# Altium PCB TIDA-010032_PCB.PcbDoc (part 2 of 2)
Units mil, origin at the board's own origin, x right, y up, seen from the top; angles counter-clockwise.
Board outline 5930.03 x 5930.03 mil, 2 copper layers (Top Layer, Bottom Layer), stack 62 mil thick; 61 components, 49 nets, 261 pads, 71 vias.
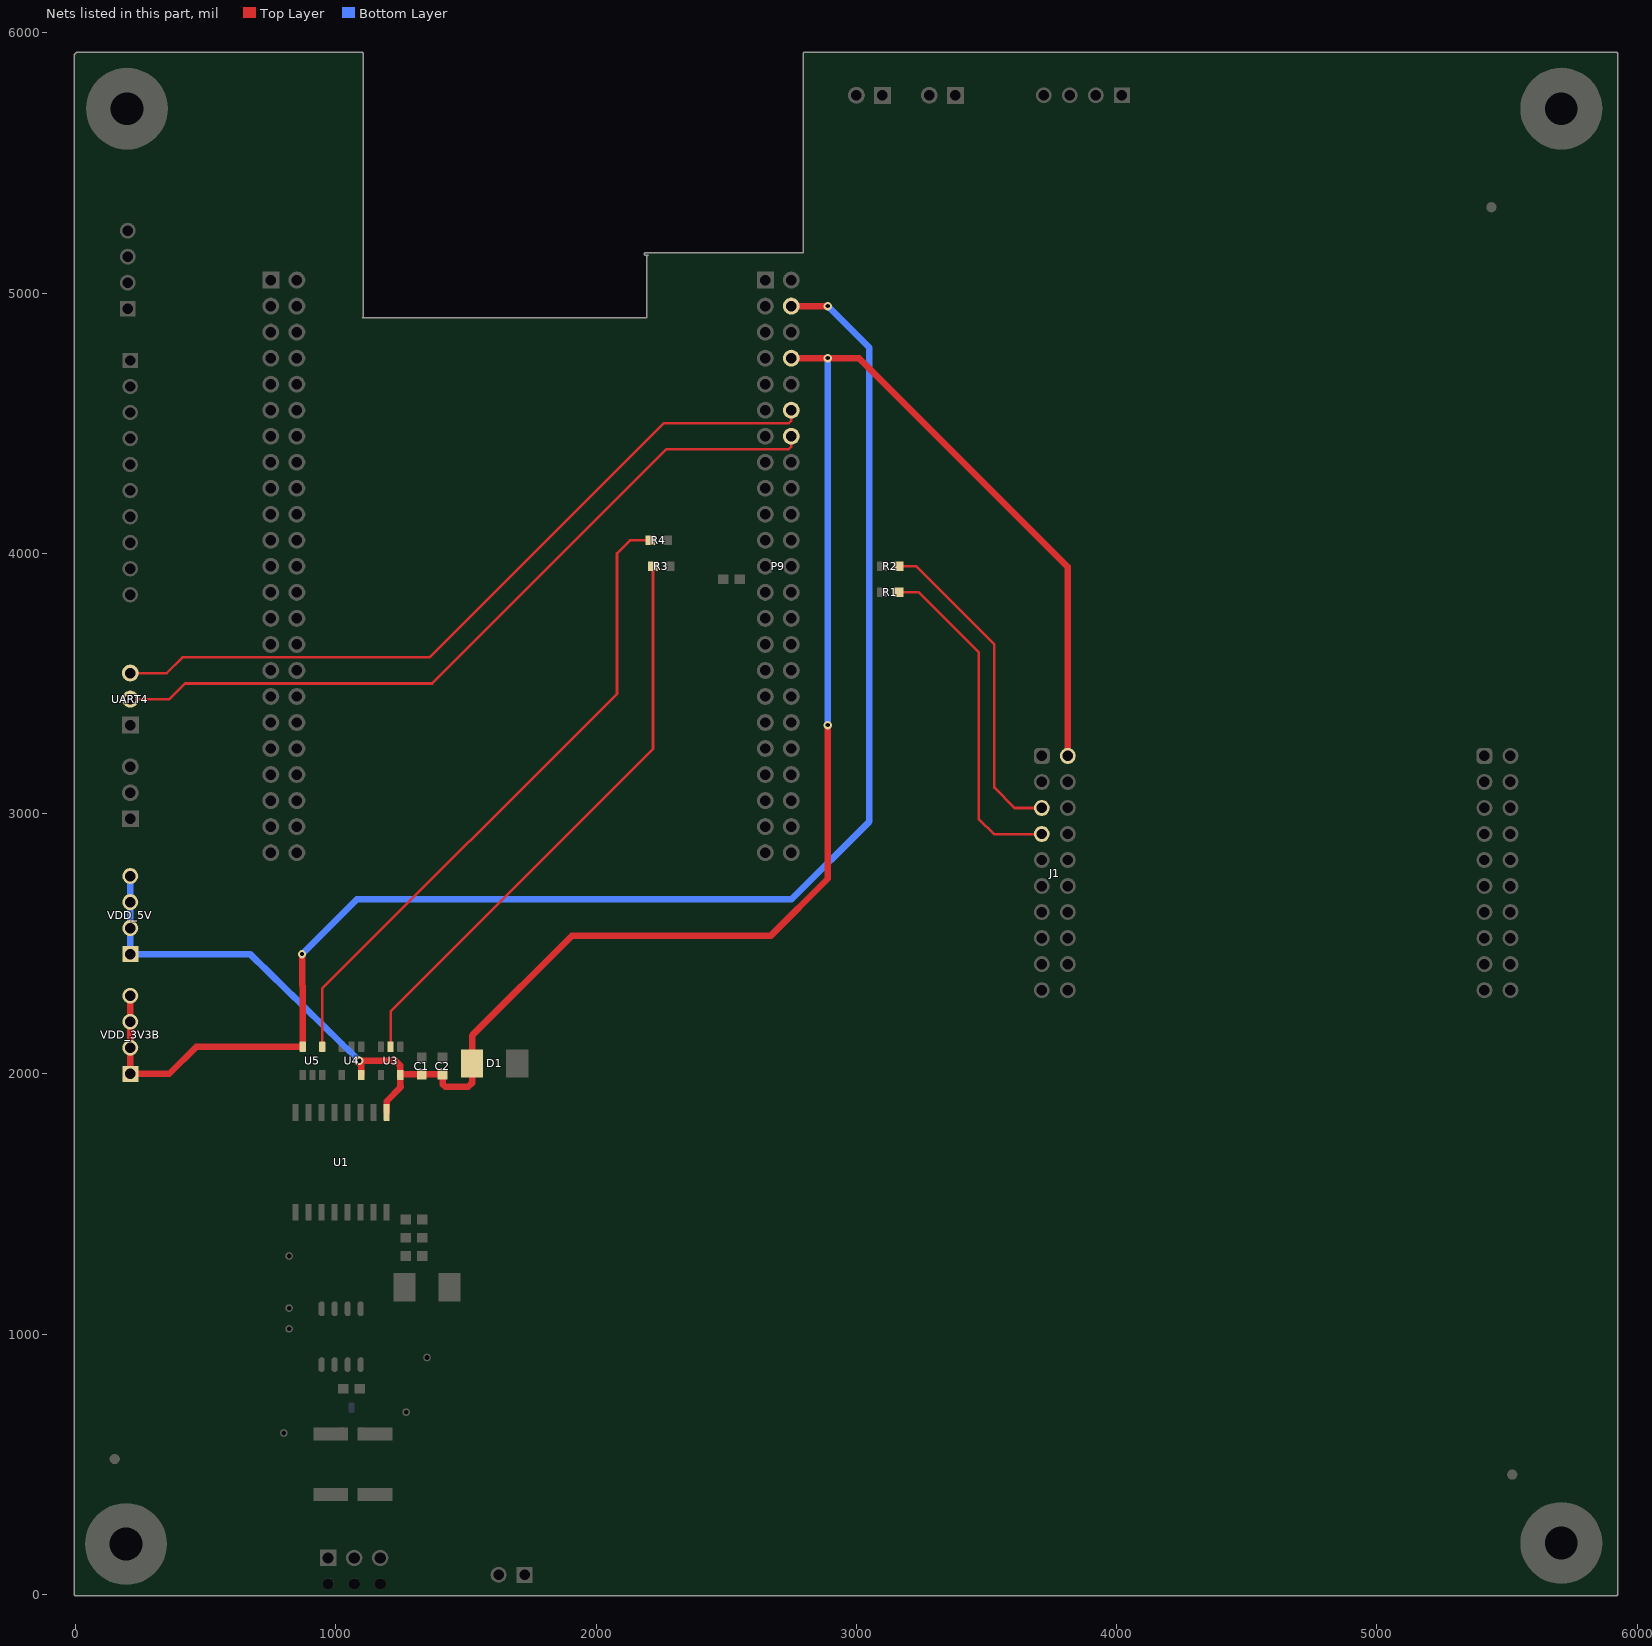
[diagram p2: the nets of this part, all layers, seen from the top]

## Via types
v1: diameter 32, hole 16, Top Layer to Bottom Layer, 71 vias

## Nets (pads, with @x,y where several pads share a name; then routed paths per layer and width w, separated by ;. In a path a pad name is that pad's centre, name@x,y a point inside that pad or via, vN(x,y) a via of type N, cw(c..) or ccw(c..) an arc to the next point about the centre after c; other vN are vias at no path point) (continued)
SYS_5V: C1.1 C2.2 D1.1 J1.2 P9.8 U1.1 U3.5 U4.5 VDD_5V.1 VDD_5V.2 VDD_5V.3 VDD_5V.4 | length 8014.7
  Top Layer w25: U4.5@1097.4,1995.87 1097.4,2032.6 1090,2040 v1(1090,2050) 1229.69,2050 1247.4,2032.28 U3.5@1247.4,1995.87 1247.4,1952.6 1250,1950 1195,1895 U1.1@1195,1851.93 ; U3.5@1250.04,1998.5 C1.1@1330,1998.5 C2.2@1410,1998.5 1410,1960 1420,1950 1508.5,1950 1522.99,1964.49 D1.1@1522.99,2040 1522.99,2147.01 1905.98,2530 2670,2530 2890,2750 v1(2890,3340) ; P9.8@2750,4750 v1(2890,4750) 3010,4750 3812.5,3947.5 3812.5,3812.2 J1.2@3812.5,3221.65
  Bottom Layer w25: VDD_5V.4@210,2760 VDD_5V.3@210,2660 VDD_5V.2@210,2560 VDD_5V.1@210,2460 670,2460 v1(1090,2050) ; v1(2890,3340) v1(2890,4750)
UART1_RXD: J1.7 R1.1 | length 1311.8
  Top Layer w10: R1.1@3161.5,3850 3240,3850 3470,3620 3470,2980 3530,2920 3710.84,2920 J1.7@3712.5,2921.65
UART1_TXD: J1.5 R2.1 | length 1257.7
  Top Layer w10: R2.1@3161.5,3950 3230,3950 3530,3650 3530,3100 3608.35,3021.65 J1.5@3712.5,3021.65
UART2_RXD: R4.1 U5.4 | length 2514.2
  Top Layer w10: U5.4@947.4,2104.13 947.4,2327.4 2080,3460 2080,4000 2130,4050 R4.1@2208.5,4050
UART2_TXD: R3.2 U3.2 | length 2263.6
  Top Layer w10: U3.2@1210,2104.13 1210,2240 2218.5,3248.5 R3.2@2218.5,3950
UART4_RXD: P9.12 UART4.3 | length 2981.8
  Top Layer w10: UART4.3@210,3540 350,3540 410,3600 1360,3600 2260,4500 2740,4500 2750,4510 P9.12@2750,4550
UART4_TXD: P9.14 UART4.2 | length 2981.8
  Top Layer w10: UART4.2@210,3440 360,3440 420,3500 1370,3500 2270,4400 2740,4400 2750,4410 P9.14@2750,4450
VDD_3V3B: P9.4 U5.5 VDD_3V3B.1 VDD_3V3B.2 VDD_3V3B.3 VDD_3V3B.4 | length 5940.2
  Top Layer w25: VDD_3V3B.4@210,2300 VDD_3V3B.3@210,2200 VDD_3V3B.2@210,2100 VDD_3V3B.1@210,2000 360,2000 464.13,2104.13 U5.5@872.6,2104.13 872.6,2337.4 870,2340 v1(870,2460) ; P9.4@2750,4950 v1(2890,4950)
  Bottom Layer w25: v1(870,2460) 1080,2670 2750,2670 3050,2970 3050,4790 v1(2890,4950)
pads on no net: FID1.1 FID2.1 FID3.1 H1.1 H2.1 H3.1 H4.1 J1.1 J1.3 J1.6 J1.8 J1.9 J1.10 J1.11 J1.12 J1.13 J1.14 J1.15 J1.16 J1.17 J1.18 J1.19 J1.20 J2.1 J2.3 J2.4 J2.5 J2.6 J2.7 J2.8 J2.9 J2.10 J2.11 J2.12 J2.13 J2.14 J2.15 J2.16 J2.17 J2.18 J2.19 J2.20 J3.4 J3.5 J3.6 P8.7 P8.8 P8.9 P8.10 P8.11 P8.12 P8.13 P8.14 P8.15 P8.16 P8.17 P8.18 P8.20 P8.25 P8.27 P8.28 P8.29 P8.30 P8.31 P8.32 P8.33 P8.34 P8.35 P8.36 P8.37 P8.38 P8.39 P8.40 P8.41 P8.42 P8.43 P8.44 P8.45 P8.46 P9.3 P9.5 P9.6 P9.7 P9.9 P9.10 P9.13 P9.15 P9.26 P9.31 P9.33 P9.34 P9.35 P9.36 P9.37 P9.38 P9.39 P9.40 P9.41 P9.42 U1.7 U3.1 U4.1 U5.1

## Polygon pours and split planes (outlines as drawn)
DGND on Top Layer "TOP_LAYER_DGND_P004" (solid, remove dead copper, pour order 4): -4.99,1829.69 0,1830 634.98,1830 1290,1830 2600.03,1830 2820,1829.69 3800,1110 3790,1100 3790,0 5910,0 5900,10 5900,5915.02 2800,5920 2800,5140 2199.45,5140 2199.45,4900.55 1105.02,4900.55 1095.8,5922.74 0,5915.02
RS485_GND on Top Layer "TOP_LAYER_RS485_GND_P000" (solid, remove dead copper, pour order 0): 0,1490 520,1490 790,1490 920,1490 1053.07,1490 1203.07,1490 1450,1490 1962.43,1019.97 1962.43,-0.03 12.43,-0.03 2.43,9.97
DGND on Bottom Layer "BOTTOM_LAYER_DGND_P006" (solid, remove dead copper, pour order 6): 0,1830 2820,1830 3790,1120 3790,1110 3790,0 3800,10 5910,10 5910,5900 5900,5910 5890,5920 2800,5910 0,5920
RS485_GND on Bottom Layer "BOTTOM_LAYER_RS485_GND_P002" (solid, remove dead copper, pour order 2): 0,1490 700,1490 1020,1490 1450,1490 1960,1019.97 1960,20 1809.53,20 0,20 0,2109.53

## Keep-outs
Keep-Out Layer:
  text ".Layer_Name" at 577,-858.49 h60

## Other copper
Top Layer:
  text ".Layer_Name" at 577,-858.49 h60
Bottom Layer:
  text ".Layer_Name" at 577,-858.49 h60

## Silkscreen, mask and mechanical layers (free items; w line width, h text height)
Top Overlay:
  region: 3930,160 3630,160 3630,60 3930,60
  text "SCA" at 2950,5660 h50.84
  text "SCL" at 3060,5660 h50.84
  text "SCA" at 3230,5660 h50.84
  text "SCL" at 3340,5660 h50.84
  text "CS0" at 3680,5660 h50.84
  text "D1" at 3790,5660 h50.84
  text "D0" at 3890.76,5659.24 h50.84
  text "SCLK" at 3970,5650 h50.84
  text "2" at 730,5120 h50.84
  text "1" at 840,5120 h50.84
  text "DGND" at 530,5040 h50.84
  text "DGND" at 930,5040 h50.84
  text "2" at 2540,5040 h50.84
  text "1" at 2830,5040 h50.84
  text "DGND" at 2950,5040 h72.83
  text "DGND" at 2310,5032.5 h72.83
  text "VDD_3V3B" at 2240,4930 h72.83
  text "VDD_3V3B" at 2950,4930 h72.83
  text "VDD_5V" at 2310,4830 h72.83
  text "VDD_5V" at 2950,4830 h72.83
  text "SYS_5V" at 2310,4740 h72.83
  text "SYS_5V" at 2950,4730 h72.83
  text "D7" at 300,4720 h50.84 r90
  text "D6" at 300,4620 h50.84 r90
  text "D5" at 299.74,4513.5 h50.84 r90
  text "D4" at 300,4420 h50.84 r90
  text "D3" at 300,4320 h50.84 r90
  text "BeagleBone Black" at 1410,4240 h72.83
  text "D2" at 299.19,4219.32 h50.84 r90
  text "D1" at 300,4120 h50.84 r90
  text "D0" at 300,4020 h50.84 r90
  text "CMD" at 300,3890 h50.84 r90
  text "CLK" at 300,3780 h50.84 r90
  text "RX" at 339.74,3512 h50.84 r90
  text "TX" at 339.74,3412 h50.84 r90
  text "J1" at 3680,3370 h72.83
  text "J2" at 5370,3370 h72.83
  text "1" at 3710,3320 h50.84
  text "21" at 3800,3320 h50.84
  text "40" at 5380,3310 h50.84
  text "20" at 5490,3310 h50.84
  text "DGND" at 340,3260 h50.84 r90
  text "GND" at 5600,3210 h50.84
  text "DIO7" at 5200,3207.7 h50.84
  text "3V3" at 3550,3200 h50.84
  text "5V" at 3900,3200 h50.84
  text "1_28" at 330,3140 h40.84 r90
  text "DIO6" at 5200,3107.7 h50.84
  text "DIO12" at 5600,3107.7 h50.84
  text "DIO23" at 3510,3100 h50.84
  text "GND" at 3900,3100 h50.84
  text "1_16" at 330,3040 h40.84 r90
  text "DIO20" at 5200,3007.7 h50.84
  text "DIO11" at 5600,3007.7 h50.84
  text "DIO2" at 3510,3000 h50.84
  text "DIO25" at 3900,3000 h50.84
  text "3_19" at 330,2940 h40.84 r90
  text "LAUNCHXL-CC1312R1" at 4270,2940 h72.83
  text "DGND" at 2380,2922.5 h72.83
  text "DGND" at 2840,2920 h72.83
  text "DIO19" at 5200,2907.7 h50.84
  text "DIO3" at 3510,2900 h50.84
  text "DIO26" at 3900,2900 h50.84
  text "DGND" at 2380,2822.5 h72.83
  text "DGND" at 2840,2820 h72.83
  text "DIO18" at 5200,2807.7 h50.84
  text "LPRST" at 5600,2807.7 h50.84
  text "DIO22" at 3510,2800 h50.84
  text "DIO27" at 3900,2800 h50.84
  text "46" at 720,2740 h50.84
  text "45" at 820,2740 h50.84
  text "46" at 2630,2740 h50.84
  text "45" at 2720,2740 h50.84
  text "BPRST" at 5200,2707.7 h50.84
  text "DIO9" at 5600,2707.7 h50.84
  text "DIO24" at 3510,2700 h50.84
  text "DIO28" at 3900,2700 h50.84
  text "TMS" at 5200,2607.7 h50.84
  text "DIO8" at 5600,2607.7 h50.84
  text "DIO10" at 3510,2600 h50.84
  text "DIO29" at 3900,2600 h50.84
  text "TCK" at 5200,2507.7 h50.84
  text "DIO13" at 5600,2507.7 h50.84
  text "DIO21" at 3510,2500 h50.84
  text "DIO30" at 3900,2500 h50.84
  text "DIO16" at 5200,2407.7 h50.84
  text "DIO14" at 5600,2407.7 h50.84
  text "DIO4" at 3510,2400 h50.84
  text "DIO17" at 5200,2307.7 h50.84
  text "DIO15" at 5600,2307.7 h50.84
  text "DIO5" at 3510,2300 h50.84
  text "DIO1" at 3900,2300 h50.84
  text "GND" at 920,280 h50.84
  text "A" at 1050,280 h50.84
  text "B" at 1160,280 h50.84
  text "RS-485" at 1260,220 h50.84 r270
  text "TIDA-010032A1" at 3640,210 h108.27
  text ".Layer_Name" at 577,-858.49 h60
Bottom Overlay:
  text ".Layer_Name" at 577,-858.49 h60
Top Paste:
  text ".Layer_Name" at 577,-858.49 h60
Bottom Paste:
  text ".Layer_Name" at 577,-858.49 h60
Top Solder:
  text ".Layer_Name" at 577,-858.49 h60
  text ".Layer_Name" at 577,-858.49 h60
Bottom Solder:
  text ".Layer_Name" at 577,-858.49 h60
Drill Guide:
  text ".Layer_Name" at 577,-858.49 h60
M1 Board Outline:
  lines w10: -10,10 0,0 ; -10,5914.98 -4.99,5920 ; 0,5920 10,5910 ; 0,0 5920,0 5920,5920 2800,5920 2800,5150 2190,5150 2200,5140 2200,4900 1090,4900 1100,4910 1100,5920 4.99,5920 0,5915.02 0,0
  text ".Layer_Name" at 577,-858.49 h60
M2 Board Dimensions:
  rectangle: 125,-400 500,-275
  rectangle: 0,-275 125,-150
  lines w7: 0,-275 1000,-275 ; 125,-400 125,-150 ; 250,-400 250,-150 ; 500,-400 500,-150 ; 750,-400 750,-150 ; 0,-400 0,-150 1000,-150 1000,-400 0,-400
  text ".Layer_Name" at 577,-858.49 h60
M3 3D STEP Top:
  text ".Layer_Name" at 577,-858.49 h60
M4 3D STEP Bottom:
  text ".Layer_Name" at 577,-858.49 h60
M5 Assembly Top:
  lines w10: -292,-930.17 6308,-930.17 ; -292,-726.83 6310,-726.83 ; -292,-523.5 -292,-1133.5 3713,-1133.5 6310,-1133.5 6310,-523.5 -291.5,-523.5 -291.5,-1133.5 1284,-1133.5 ; 2173,-1133.5 2173,-523.5 ; 3440,-726.83 3440,-523.5 ; 4280,-726.83 4280,-523.5 ; 4902,-1140 4902,-937.17
  text "COMPONENTS MARKED 'DNP' SHOULD NOT BE POPULATED." at 1153.5,-318.5 h60
  text "ASSEMBLY VARIANT:" at 1153,-434 h60
  text ".VariantName" at 2189,-434 h60
  text "PCB VIEWED FROM TOP SIDE" at -228.5,-655.67 h60
  text "BOARD #:" at 2248,-655.67 h60
  text ".PRJ_Number" at 2793.5,-655.67 h60
  text "REV:" at 3638,-655.67 h60
  text ".PCB_Rev" at 3929.5,-655.67 h60
  text "SVN REV:" at 4476,-655.67 h60
  text ".VersionControl_RevNumber" at 4982,-655.67 h60
  text "TID #:" at 2248,-859 h60
  text ".TID" at 2793.5,-859 h60
  text "PLOT NAME =" at -228.5,-1064.34 h60
  text ".plot_File_Name" at 577,-1064.34 h60
  text "GENERATED    :" at 2250,-1064.34 h60
  text ".Print_Date" at 3119.5,-1064.34 h60
  text ".Print_Time" at 3848.5,-1064.34 h60
  text "TEXAS INSTRUMENTS" at 5113,-1064.34 h60
M6 Assembly Bottom:
  lines w10: -292.5,-727.33 6309.5,-727.33 ; -290.5,-930.67 6309.5,-930.67 ; 1115.5,-1140.5 1115.5,-937.67 ; 1737.5,-727.33 1737.5,-524 ; 2577.5,-727.33 2577.5,-524 ; 3844.5,-1134 3844.5,-524 ; 4733.5,-1134 6309,-1134 6309,-524 -292.5,-524 -292.5,-1134 2304.5,-1134 6309.5,-1134 6309.5,-524
  text "COMPONENTS MARKED 'DNP' SHOULD NOT BE POPULATED." at 6102,-318 h60
  text ".VariantName" at 5058,-434 h60
  text "ASSEMBLY VARIANT:" at 6097,-434 h60
  text ".VersionControl_RevNumber" at 1035.5,-656.17 h60
  text "SVN REV:" at 1541.5,-656.17 h60
  text ".PCB_Rev" at 2088,-656.17 h60
  text "REV:" at 2379.5,-656.17 h60
  text ".PRJ_Number" at 3224,-656.17 h60
  text "BOARD #:" at 3769.5,-656.17 h60
  text "PCB VIEWED FROM BOTTOM SIDE" at 6246,-656.17 h60
  text ".TID" at 3224,-859.5 h60
  text "TID #:" at 3769.5,-859.5 h60
  text "TEXAS INSTRUMENTS" at 904.5,-1064.84 h60
  text ".Print_Time" at 2169,-1064.84 h60
  text ".Print_Date" at 2898,-1064.84 h60
  text "GENERATED    :" at 3767.5,-1064.84 h60
  text ".plot_File_Name" at 5440.5,-1064.84 h60
  text "PLOT NAME =" at 6246,-1064.84 h60
M9 Title Sheet:
  drawing of 57 lines, arcs and shapes, not listed
  text "1" at 739.84,8036.5 h70
  text "2" at 3235.5,8036.5 h70
  text "3" at 5724.84,8036.5 h70
  text "4" at 8231.51,8036.5 h70
  text "5" at 10730.5,8036.5 h70
  text "6" at 13235.5,8036.5 h70
  text "A" at -416.5,6893.5 h70
  text "A" at 14383.5,6893.5 h70
  text "B" at -416.5,4513.5 h70
  text "B" at 14383.5,4513.5 h70
  text "C" at -416.5,2138.5 h70
  text "C" at 14383.5,2138.5 h70
  text "PROJECT TITLE:" at 11343.5,277.5 h45
  text ".PRJ_Title" at 11393.5,144.17 h70
  text "DESIGNED FOR:" at 11343.5,-23.5 h45
  text ".PRJ_Customer" at 11393.5,-163.5 h70
  text "D" at -416.5,-231.5 h70
  text "D" at 14383.5,-231.5 h70
  text "FILE NAME:" at 11343.5,-323.5 h45
  text ".PCB_File_Name_No_Path" at 11393.5,-443.5 h70
  text "Texas Instruments (TI) and/or its licensors do not warrant the accuracy or completeness of this specification" at 6374,-605.34 h45
  text "ENGINEER:" at 11343.5,-613.5 h45
  text "LAYOUT BY:" at 12848.5,-613.5 h45
  text "or any information contained therein. TI and/or its licensors do not warrant that this design will meet" at 6329.01,-718 h45
  text ".PRJ_Engineer" at 11393.5,-768.49 h70
  text ".PCB_Layout" at 12899,-768.49 h70
  text "the specifications, will be suitable for your application or fit for any particular purpose, or will operate in" at 6329.01,-830.67 h45
  text ".Layer_Name" at 577,-858.49 h60
  text "ALTIUM DESIGNER VERSION:" at 12848.5,-923.5 h45
  text "an implementation. TI and/or its licensors do not warrant that the design is production worthy. You should" at 6329.01,-943.33 h45
  text "completely validate and test your design implementation to confirm the system functionality for your application." at 6374,-1056 h45
  text ".print_Scale" at 11393.5,-1056.83 h70
  text ".Application_BuildNumber" at 12899,-1056.83 h70
  text "1" at 739.84,-1263.5 h70
  text "2" at 3235.5,-1263.5 h70
  text "3" at 5724.84,-1263.5 h70
  text "4" at 8231.51,-1263.5 h70
  text "5" at 10730.5,-1263.5 h70
  text "6" at 13235.5,-1263.5 h70
M10 Fab Notes:
  drawing of 173 lines, arcs and shapes, not listed
  text "DESIGN INFORMATION" at 12378.02,6201 h60
  text "MIN. TRACK WIDTH:" at 11733.46,6021 h60
  text "8" at 12829.7,6021 h60
  text "MIL" at 12984.46,6021 h60
  text "MIN. CLEARANCE:" at 11733.46,5889 h60
  text "0.2" at 12769.7,5889 h60
  text "mm" at 12984.46,5889 h60
  text "MIN. VIA PAD SIZE:" at 11733.46,5757 h60
  text "24" at 12799.71,5757 h60
  text "MIL" at 12984.46,5757 h60
  text "0.05mm (2MIL)" at 12428.46,5615.29 h60
  text "MINIMUM ANNULAR RING" at 11404.23,5611 h60
  text "EXTERNAL" at 13136.46,5611 h60
  text "PER" at 11604.23,5493 h60
  text "IPC-D-275 CLASS 2 LEVEL C" at 11824.23,5493 h60
  text "MIL, HOLES" at 13312.46,5380.71 h60
  text "+/-" at 12920,5380 h60
  text "+/-" at 13774,5380 h60
  text "REGISTRATION TOLERANCES:" at 11404.23,5375 h60
  text "METAL" at 12604,5375 h60
  text "5" at 13180.2,5375 h60
  text "3" at 14013.2,5375 h60
  text "MIL" at 14129.46,5375 h60
  text "+/-" at 13774,5262 h60
  text "HOLE SIZE TOLERANCE (UNLESS OTHERWISE SPECIFIED):" at 11404.23,5257 h60
  text "3" at 14013.2,5257 h60
  text "MIL" at 14129.46,5257 h60
  text "MATERIAL:" at 11329.46,5047.54 h60
  text "FR-4 High Tg" at 12315.9,4907.21 h60
  text "FR-408" at 11750.46,4898.64 h60
  text "OTHER" at 13238.46,4898.64 h60
  text "X" at 12161,4895 h60
  text "62 MIL (1.6mm) +/-10%" at 12070.56,4735.92 h60
  text "THICKNESS:" at 11404.23,4731.64 h60
  text "X" at 11942.4,4731.64 h60
  text "OTHER" at 13355.46,4731.64 h60
  text "TOLERANCE:" at 11404.23,4573.64 h60
  text "X" at 12243.53,4573.64 h60
  text "ANSI IPC-6012 TYPE 3 CLASS 2" at 12430.48,4573.64 h60
  text "OTHER +/-" at 12430.46,4417.64 h60
  text "BOW & TWIST:" at 11404.23,4260.64 h60
  text "X" at 12243.53,4260.64 h60
  text "ANSI IPC-6012 TYPE 3 CLASS 2" at 12430.48,4260.64 h60
  text "OTHER +/-" at 12430.46,4102.13 h60
  text "DRILLING:" at 11329.46,3963.64 h60
  text "REFERENCE:" at 11404.23,3846.64 h60
  text "X" at 12052.46,3846.64 h60
  text "AS SHOWN" at 12239.46,3846.64 h60
  text "X" at 12953.46,3846.64 h60
  text "NC_DRILL FILES" at 13090.46,3846.64 h60
  text "PTH COPPER THICKNESS:" at 11404.23,3688.64 h60
  text "X" at 12534.46,3688.64 h60
  text "20-30 um" at 12671.46,3688.64 h60
  text "OTHER" at 13388.46,3688.64 h60
  text "BOARD FINISH:" at 11329.46,3529.64 h60
  text "SILKSCREEN:" at 11484.68,3411.64 h60
  text "X" at 12433.46,3411.64 h60
  text "TOP" at 12559.46,3411.64 h60
  text "X" at 12943.46,3411.64 h60
  text "BOTTOM" at 13070.46,3411.64 h60
  text "SILKSCREEN COLOR:" at 11484.68,3244.64 h60
  text "X" at 12432.42,3244.64 h60
  text "WHITE" at 12559.46,3244.64 h60
  text "OTHER" at 13070.46,3244.64 h60
  text "X" at 12563.42,3085.44 h60
  text "GREEN" at 12690.46,3085.44 h60
  text "OTHER" at 13308.46,3085.44 h60
  text "SOLDER RESIST COLOR:" at 11484.68,3074.64 h60
  text "X" at 12563.42,2915.44 h60
  text "MATTE" at 12690.46,2915.44 h60
  text "SEMI-GLOSS" at 13308,2914.8 h60
  text "IMMERSION GOLD (ENIG)" at 12390.46,2726.92 h60
  text "ENEPIG" at 13728,2723.64 h60
  text "SURFACE FINISH:" at 11329.46,2722.64 h60
  text "X" at 12203.51,2722.64 h60
  text "IMM. TIN/SILVER OR EQUIV" at 11659,2565.64 h60
  text "OTHER" at 13090.46,2565.64 h60
  text "ARRAY/PANEL:" at 11329.46,2386.64 h60
  text "CUT AND TRIM PER M1 BOARD OUTLINE" at 12390.46,2382.35 h60
  text "N.C. ROUTE" at 12390.46,2230.64 h60
  text "X" at 13069.46,2230.64 h60
  text "V. SCORE" at 13256.46,2230.64 h60
  text "CERTIFICATION:" at 11329.46,2093.64 h60
  text "MATERIALS AND WORKMANSHIP FOR ALL PCBS" at 12054.46,2093.64 h60
  text "TO MEET OR EXCEED THE REQUIREMENTS OF:" at 12054.46,1995.64 h60
  text "X" at 11680.96,1859.13 h60
  text "ANSI IPC-A-600F CLASS ->" at 11819.96,1859.13 h60
  text "X" at 13459.02,1859.13 h60
  text "2" at 13577.96,1859.14 h60
  text "1" at 13262.96,1857.64 h60
  text "3" at 13931.96,1857.64 h60
  text "X" at 12495.02,1699.64 h60
  text "RoHS" at 12631.96,1699.64 h60
  text "OTHER" at 13276.36,1699.64 h60
  text "PER ORDER" at 13673.42,1699.64 h60
  text "ALL BOARDS MUST MEET OR EXCEED UL94-V0 REQUIREMENTS." at 11357,1534 h60
  text "PCB MUST BEAR THE UL94V-0 UL REGISTERED MATERIAL ID NUMBER" at 11357,1414 h60
  text "ADDITIONAL REQUIREMENTS:" at 11329.46,1240.64 h60
  text "MICROSECTION:" at 11404.23,1125.64 h60
  text "YES" at 12309.96,1125.64 h60
  text "REQUIRED" at 13171.46,969.49 h60
  text "BARE BOARD ELEC. TEST:" at 11404.23,966.64 h60
  text "NONE" at 12709.96,966.64 h60
  text "X" at 13044.46,966.64 h60
  text "PER ORDER" at 13763.46,966.64 h60
  text ".Layer_Name" at 577,-858.49 h60
M11 Gerber Information:
  lines w10: -292,-930.17 6308,-930.17 ; -292,-726.83 6310,-726.83 ; -292,-523.5 -292,-1133.5 3713,-1133.5 6310,-1133.5 6310,-523.5 -291.5,-523.5 -291.5,-1133.5 1284,-1133.5 ; 2173,-1133.5 2173,-523.5 ; 3440,-726.83 3440,-523.5 ; 4280,-726.83 4280,-523.5 ; 4902,-1140 4902,-937.17
  text "ALL ARTWORK VIEWED FROM TOP SIDE" at -228.5,-655.67 h60
  text "BOARD #:" at 2248,-655.67 h60
  text ".PRJ_Number" at 2793.5,-655.67 h60
  text "REV:" at 3638,-655.67 h60
  text ".PCB_Rev" at 3929.5,-655.67 h60
  text "SVN REV:" at 4476,-655.67 h60
  text ".VersionControl_RevNumber" at 4982,-655.67 h60
  text "LAYER NAME =" at -228.5,-858.49 h60
  text "TID #:" at 2248,-859 h60
  text ".TID" at 2793.5,-859 h60
  text "PLOT NAME =" at -228.5,-1064.34 h60
  text ".plot_File_Name" at 577,-1064.34 h60
  text "GENERATED    :" at 2250,-1064.34 h60
  text ".Print_Date" at 3119.5,-1064.34 h60
  text ".Print_Time" at 3848.5,-1064.34 h60
  text "TEXAS INSTRUMENTS" at 5113,-1064.34 h60
M12 Stackup:
  drawing of 191 lines, arcs and shapes, not listed
  text "Layer" at 9790.34,7830 h60
  text "Name" at 10200.26,7830 h60
  text "Material" at 11130,7830 h60
  text "Thickness" at 11989.77,7830 h60
  text "Constant" at 12639.6,7830 h60
  text "Board Layer Stack" at 13209.46,7830 h60
  text "1" at 9790.34,7710 h60
  text "Top Overlay" at 10200.26,7710 h60
  text "2" at 9790.34,7590 h60
  text "Top Solder" at 10200.26,7590 h60
  text "Solder Resist" at 11130,7590 h60
  text "0.40mil" at 11989.77,7590 h60
  text "3.5" at 12639.6,7590 h60
  text "3" at 9790.34,7470 h60
  text "Top Layer" at 10200.26,7470 h60
  text "Copper" at 11130,7470 h60
  text "1.40mil" at 11989.77,7470 h60
  text "4" at 9790.34,7350 h60
  text "Dielectric1" at 10200.26,7350 h60
  text "FR-4" at 11130,7350 h60
  text "59.20mil" at 11989.77,7350 h60
  text "4.8" at 12639.6,7350 h60
  text "5" at 9790.34,7230 h60
  text "Bottom Layer" at 10200.26,7230 h60
  text "Copper" at 11130,7230 h60
  text "1.40mil" at 11989.77,7230 h60
  text "6" at 9790.34,7110 h60
  text "Bottom Solder" at 10200.26,7110 h60
  text "Solder Resist" at 11130,7110 h60
  text "0.40mil" at 11989.77,7110 h60
  text "3.5" at 12639.6,7110 h60
  text "7" at 9790.34,6990 h60
  text "Bottom Overlay" at 10200.26,6990 h60
  text ".Layer_Name" at 577,-858.49 h60
M13 Component Bodies Top:
  text ".Layer_Name" at 577,-858.49 h60
M14 Component Bodies Bottom:
  text ".Layer_Name" at 577,-858.49 h60
M15 Courtyards Top:
  text ".Layer_Name" at 577,-858.49 h60
M16 Courtyards Bottom:
  text ".Layer_Name" at 577,-858.49 h60
Drill Drawing:
  circle w10: c6784.88,4016.94 r13.28
  circle w10: c6784.88,4016.94 r22.14
  circle w10: c6784.88,3618.45 r22.14
  lines w10: 6762.74,3695.93 6784.88,3707 6807.02,3695.93 6795.95,3718.07 6807.02,3740.21 6784.88,3729.14 6762.74,3740.21 6773.81,3718.07 6762.74,3695.93 ; 6762.74,3839.83 6807.02,3839.83 6784.88,3795.55 6762.74,3839.83 ; 6762.74,3906.25 6773.81,3906.25 6773.81,3895.18 6795.95,3895.18 6795.95,3906.25 6807.02,3906.25 6807.02,3928.38 6795.95,3928.38 6795.95,3939.45 6773.81,3939.45 6773.81,3928.38 6762.74,3928.38 6762.74,3906.25 ; 6762.74,4094.42 6762.74,4105.49 6773.81,4116.56 6762.74,4127.63 6762.74,4138.7 6773.81,4138.7 6784.88,4127.63 6795.95,4138.7 6807.02,4138.7 6807.02,4127.63 6795.95,4116.56 6807.02,4105.49 6807.02,4094.42 6795.95,4094.42 6784.88,4105.49 6773.81,4094.42 6762.74,4094.42 ; 6762.74,4194.04 6807.02,4194.04 6807.02,4238.32 6762.74,4238.32 6762.74,4194.04 ; 6762.74,4304.74 6773.81,4304.74 6784.88,4293.67 6795.95,4304.74 6807.02,4304.74 6795.95,4315.8 6807.02,4326.87 6795.95,4326.87 6784.88,4337.94 6773.81,4326.87 6762.74,4326.87 6773.81,4315.8 6762.74,4304.74 ; 6771.6,4202.9 6798.16,4202.9 6798.16,4229.46 6771.6,4229.46 6771.6,4202.9
  lines w12: 6721.98,3566.42 9834.92,3566.42 ; 6721.98,4363.4 9834.92,4363.4 ; 7037.61,3466.8 7037.61,4463.02 ; 7354.8,3466.8 7354.8,4463.02 ; 7976.54,3466.8 7976.54,4463.02 ; 8220.86,3466.8 8220.86,4463.02 ; 8581.2,3466.8 8581.2,4463.02 ; 9290.71,3466.8 9290.71,4463.02 ; 6721.98,3466.8 9834.92,3466.8 9834.92,4463.02 6721.98,4463.02 6721.98,3466.8
  text "Symbol" at 6781.75,4393.29 h72
  text "Quantity" at 7067.5,4393.29 h72
  text "Finished Hole Size" at 7384.68,4393.29 h72
  text "Plated" at 8006.43,4393.29 h72
  text "Hole Type" at 8250.75,4393.29 h72
  text "Drill Layer Pair" at 8611.09,4393.29 h72
  text "Hole Tolerance" at 9320.6,4393.29 h72
  text "3" at 7067.5,4293.67 h60
  text "43.31mil (1.100mm)" at 7384.68,4293.67 h60
  text "NPTH" at 8006.43,4293.67 h60
  text "Round" at 8250.75,4293.67 h60
  text "Top Layer - Bottom Layer" at 8611.09,4293.67 h60
  text "71" at 7067.5,4194.04 h60
  text "16.00mil (0.406mm)" at 7384.68,4194.04 h60
  text "PTH" at 8006.43,4194.04 h60
  text "Round" at 8250.75,4194.04 h60
  text "Top Layer - Bottom Layer" at 8611.09,4194.04 h60
  text "6" at 7067.5,4094.42 h60
  text "17.72mil (0.450mm)" at 7384.68,4094.42 h60
  text "PTH" at 8006.43,4094.42 h60
  text "Round" at 8250.75,4094.42 h60
  text "Top Layer - Bottom Layer" at 8611.09,4094.42 h60
  text "10" at 7067.5,3994.8 h60
  text "39.37mil (1.000mm)" at 7384.68,3994.8 h60
  text "PTH" at 8006.43,3994.8 h60
  text "Round" at 8250.75,3994.8 h60
  text "Top Layer - Bottom Layer" at 8611.09,3994.8 h60
  text "118" at 7067.5,3895.18 h60
  text "40.00mil (1.016mm)" at 7384.68,3895.18 h60
  text "PTH" at 8006.43,3895.18 h60
  text "Round" at 8250.75,3895.18 h60
  text "Top Layer - Bottom Layer" at 8611.09,3895.18 h60
  text "42" at 7067.5,3795.55 h60
  text "40.16mil (1.020mm)" at 7384.68,3795.55 h60
  text "PTH" at 8006.43,3795.55 h60
  text "Round" at 8250.75,3795.55 h60
  text "Top Layer - Bottom Layer" at 8611.09,3795.55 h60
  text "3" at 7067.5,3695.93 h60
  text "43.31mil (1.100mm)" at 7384.68,3695.93 h60
  text "PTH" at 8006.43,3695.93 h60
  text "Round" at 8250.75,3695.93 h60
  text "Top Layer - Bottom Layer" at 8611.09,3695.93 h60
  text "4" at 7067.5,3596.31 h60
  text "125.98mil (3.200mm)" at 7384.68,3596.31 h60
  text "PTH" at 8006.43,3596.31 h60
  text "Round" at 8250.75,3596.31 h60
  text "Top Layer - Bottom Layer" at 8611.09,3596.31 h60
  text "257 Total" at 7067.5,3496.69 h60
  text ".Layer_Name" at 577,-858.49 h60
M17 Embedded Cavity:
  text ".Layer_Name" at 577,-858.49 h60
M18 Embedded Assembly:
  text ".Layer_Name" at 577,-858.49 h60
M19 Embedded Keepout:
  text ".Layer_Name" at 577,-858.49 h60

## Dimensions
0,0 to -5.01,0 on M2 Board Dimensions
0,0 to -0.03,5920.03 on M2 Board Dimensions
0,-400 to 1000,-400 on M2 Board Dimensions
